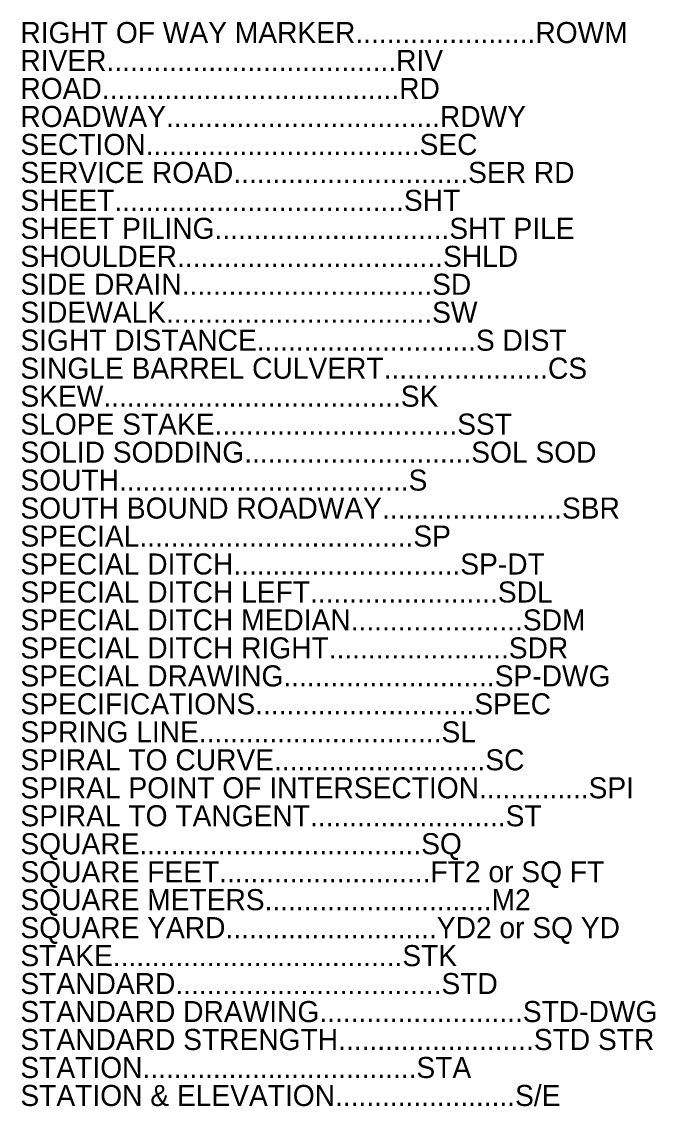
# Model space of a CAD drawing. Extents: x 0 to 1700, y 31 to 1131.
# Drawn here: x 902 to 1112.5, y 399.9 to 760.4 of the extents above; entities that cross this region are included whole.
import ezdxf

# ---------------------------------------------------------------- set-up
doc = ezdxf.new("R2010")
doc.units = 0
doc.layers.add('Level 1', color=7, linetype='Continuous')

msp = doc.modelspace()

# ---------------------------------------------------------------- texts
at = {"layer": 'Level 1'}
for s, p in [('RIGHT OF WAY MARKER.......................ROWM', (901.56, 753.29)), ('RIVER.....................................RIV', (901.56, 744)), ('ROAD......................................RD', (901.56, 734.7)), ('ROADWAY...................................RDWY', (901.56, 725.4)), ('SECTION...................................SEC', (901.56, 716.11)), ('SERVICE ROAD..............................SER RD', (901.56, 706.81)), ('SHEET.....................................SHT', (901.56, 697.52)), ('SHEET PILING..............................SHT PILE', (901.56, 688.22)), ('SHOULDER..................................SHLD', (901.56, 678.92)), ('SIDE DRAIN................................SD', (901.56, 669.63)), ('SIDEWALK..................................SW', (901.56, 660.33)), ('SIGHT DISTANCE............................S DIST', (901.56, 651.04)), ('SINGLE BARREL CULVERT.....................CS', (901.56, 641.74)), ('SKEW......................................SK', (901.56, 632.44)), ('SLOPE STAKE...............................SST', (901.56, 623.15)), ('SOLID SODDING.............................SOL SOD', (901.56, 613.85)), ('SOUTH.....................................S', (901.56, 604.56)), ('SOUTH BOUND ROADWAY.......................SBR', (901.56, 595.26)), ('SPECIAL...................................SP', (901.56, 585.96)), ('SPECIAL DITCH.............................SP-DT', (901.56, 576.67)), ('SPECIAL DITCH LEFT........................SDL', (901.56, 567.37)), ('SPECIAL DITCH MEDIAN......................SDM', (901.56, 558.08)), ('SPECIAL DITCH RIGHT.......................SDR', (901.56, 548.78)), ('SPECIAL DRAWING...........................SP-DWG', (901.56, 539.48)), ('SPECIFICATIONS............................SPEC', (901.56, 530.19)), ('SPRING LINE...............................SL', (901.56, 520.89)), ('SPIRAL TO CURVE...........................SC', (901.56, 511.6)), ('SPIRAL POINT OF INTERSECTION..............SPI', (901.56, 502.3)), ('SPIRAL TO TANGENT.........................ST', (901.56, 493)), ('SQUARE....................................SQ', (901.56, 483.71)), ('SQUARE FEET...........................FT2 or SQ FT', (901.56, 474.41)), ('SQUARE METERS.............................M2', (901.56, 465.12)), ('SQUARE YARD...........................YD2 or SQ YD', (901.56, 455.82)), ('STAKE.....................................STK', (901.56, 446.52)), ('STANDARD..................................STD', (901.56, 437.23)), ('STANDARD DRAWING..........................STD-DWG', (901.56, 427.93)), ('STANDARD STRENGTH.........................STD STR', (901.56, 418.64)), ('STATION...................................STA', (901.56, 409.34)), ('STATION & ELEVATION.......................S/E', (901.56, 400.04))]:
    msp.add_text(s, height=7, dxfattribs=at).set_placement(p)

doc.saveas('drawing.dxf')
